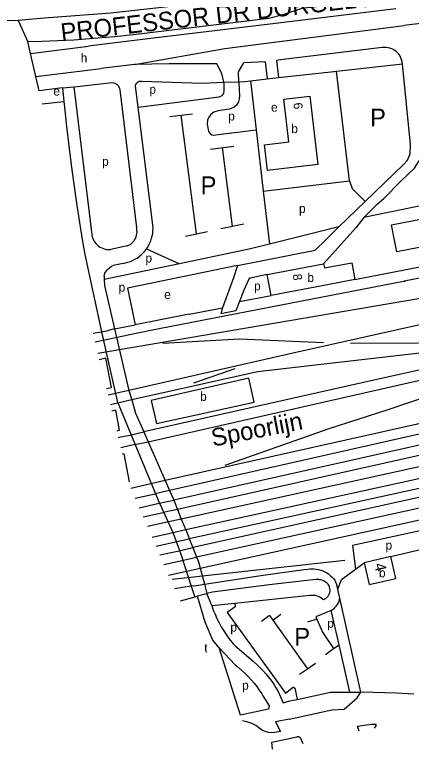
# Model space of a CAD drawing. Extents: x 161494 to 163033, y 383688 to 384862.
# Drawn here: x 161670.9 to 161849.3, y 383687.6 to 384018.2 of the extents above; entities that cross this region are included whole.
import ezdxf

# ---------------------------------------------------------------- set-up
doc = ezdxf.new("R2010")
doc.units = 0
for name, color, linetype in [('BLT_Basislijn', 7, 'Continuous'), ('BLT_Bebouwing', 7, 'Continuous'), ('BLT_Centroide', 7, 'Continuous'), ('BLT_Huisnummer', 7, 'Continuous'), ('BLT_Spoorlijn', 7, 'Continuous'), ('BLT_Straatnaam_hoofdweg', 7, 'Continuous'), ('BLT_Tekst_parkeren', 7, 'Continuous'), ('BLT_Vlakafsluiter', 7, 'Continuous'), ('BLT_Waternaam_spoorwegen', 7, 'Continuous')]:
    doc.layers.add(name, color=color, linetype=linetype)

msp = doc.modelspace()

# ---------------------------------------------------------------- linework, layer by layer
at = {"layer": 'BLT_Basislijn'}
for p, q in [((161765.4, 384002.94), (161846.02, 384013.32)), ((161677.97, 384000.74), (161704.06, 384004.05)), ((161836.15, 384003.38), (161790.39, 383997.8)), ((161783.48, 383996.91), (161773.88, 383996.43)), ((161783.48, 383996.91), (161784.41, 383989.24)), ((161680.37, 383990.38), (161709.82, 383994)), ((161724.78, 383995.79), (161709.82, 383994)), ((161815.65, 383992.77), (161845.3, 383996.01)), ((161784.41, 383989.24), (161789.51, 383989.82)), ((161789.51, 383989.82), (161814.36, 383992.62)), ((161814.36, 383992.62), (161815.65, 383992.77)), ((161697.71, 383985.74), (161714.8, 383987.57)), ((161774.42, 383988.12), (161776.92, 383988.4)), ((161776.92, 383988.4), (161784.41, 383989.24)), ((161692.4, 383985.17), (161681.87, 383983.86)), ((161692.4, 383985.17), (161697.71, 383985.74)), ((161692.4, 383985.17), (161693.01, 383979.05)), ((161705.81, 383917.86), (161697.71, 383985.74)), ((161726.41, 383976.48), (161725.22, 383985.97)), ((161683.23, 383977.98), (161693.01, 383979.05)), ((161733.03, 383923.45), (161726.41, 383976.48)), ((161740.72, 383972.29), (161750.81, 383973.53)), ((161752.62, 383919.49), (161745.77, 383972.91)), ((161758.96, 383957.71), (161769.41, 383959.02)), ((161764.19, 383958.36), (161768.74, 383922.99)), ((161782.69, 383938.81), (161785.47, 383914.89)), ((161885.02, 383938.77), (161827.95, 383926.88)), ((161763.6, 383921.88), (161773.88, 383924.1)), ((161827.95, 383926.88), (161824.29, 383922.18)), ((161747.64, 383918.45), (161757.6, 383920.53)), ((161824.29, 383922.18), (161809.85, 383905.98)), ((161721.43, 383914.07), (161714.06, 383912.5)), ((161730.16, 383912.76), (161744.95, 383906.09)), ((161719.64, 383906.25), (161715.18, 383905.36)), ((161711.14, 383900.44), (161711.12, 383899.03)), ((161772.01, 383889.06), (161786.28, 383891.79)), ((161772.01, 383889.06), (161770.41, 383884.87)), ((161749.36, 383883.42), (161764.42, 383886.22)), ((161764.42, 383886.22), (161763.53, 383883.59)), ((161770.41, 383884.87), (161763.53, 383883.59)), ((161749.36, 383883.42), (161725, 383878.57)), ((161715.71, 383876.72), (161725, 383878.57)), ((161706.18, 383874.78), (161709.88, 383875.43)), ((161709.88, 383875.43), (161712.87, 383876.09)), ((161715.71, 383876.72), (161712.87, 383876.09)), ((161715.71, 383876.72), (161722.27, 383849.1)), ((161824.12, 383768.62), (161828.04, 383771.52)), ((161751.61, 383761.13), (161756.21, 383761.84)), ((161756.21, 383761.84), (161757.29, 383757.74)), ((161807.74, 383763.94), (161806.33, 383763.91)), ((161814.83, 383763.63), (161815.99, 383760.97)), ((161750.28, 383760.93), (161742.81, 383759.77)), ((161751.61, 383761.13), (161750.28, 383760.93)), ((161750.28, 383760.93), (161751.84, 383756.07)), ((161816.29, 383759.59), (161815.99, 383760.97)), ((161817.18, 383755.63), (161816.29, 383759.59)), ((161751.84, 383756.07), (161745.25, 383754.16)), ((161753.15, 383756.45), (161751.84, 383756.07)), ((161753.12, 383756.56), (161757.29, 383757.74)), ((161753.15, 383756.45), (161753.12, 383756.56)), ((161759.49, 383752.21), (161757.29, 383757.74)), ((161769.84, 383753.32), (161803.68, 383756.95)), ((161826.62, 383713.33), (161817.18, 383755.63)), ((161759.49, 383752.21), (161769.84, 383753.32)), ((161786.97, 383745.72), (161790.65, 383748.43)), ((161814.84, 383742.96), (161813.21, 383750.07)), ((161785.52, 383747.76), (161781.9, 383745.1)), ((161785.52, 383747.76), (161786.97, 383745.72)), ((161786.97, 383745.72), (161802.57, 383723.78)), ((161806.73, 383746.14), (161802.54, 383744.71)), ((161816.75, 383734.59), (161814.84, 383742.96)), ((161762.87, 383733.18), (161770, 383725.61)), ((161772.4, 383702.86), (161762.87, 383733.18)), ((161770.81, 383733.46), (161778.34, 383727.09)), ((161810.62, 383730.25), (161814.34, 383732.89)), ((161814.34, 383732.89), (161816.75, 383734.59)), ((161821.62, 383713.28), (161816.75, 383734.59)), ((161802.57, 383723.78), (161806.25, 383726.35)), ((161799.02, 383721.31), (161802.57, 383723.78)), ((161821.62, 383713.28), (161826.62, 383713.33)), ((161794.69, 383709.36), (161797.89, 383710.05)), ((161785.06, 383705.7), (161772.4, 383702.86)), ((161799.31, 383692.83), (161800.51, 383690.22))]:
    msp.add_line(p, q, dxfattribs=at)
for points in [[(161959.65, 384027.27), (161916.99, 384022.03), (161846.02, 384013.32)], [(161835.45, 384025.19), (161800.1, 384020.96), (161791.09, 384018)], [(161739.79, 384021.71), (161714.13, 384018.78), (161684.15, 384016.64), (161672.41, 384015.53)], [(161842.35, 384020.82), (161788.17, 384014.19)], [(161791.09, 384018), (161785.18, 384016.45), (161725.46, 384009.27), (161715.75, 384008.14), (161704.48, 384007.29)], [(161538.09, 384009.41), (161555.72, 384011.42), (161572.01, 384013.43), (161594.77, 384014.55), (161646.33, 384015.67), (161672.41, 384015.53)], [(161788.17, 384014.19), (161729.55, 384007.15), (161704.06, 384004.05)], [(161704.48, 384007.29), (161697.55, 384006.73), (161683.11, 384006.03), (161676.77, 384005.94)], [(161845.3, 383996.01), (161845.2, 383996.81), (161845.03, 383997.59), (161844.77, 383998.35), (161844.45, 383999.08), (161844.05, 383999.78), (161843.59, 384000.43), (161843.06, 384001.03), (161842.48, 384001.58), (161841.84, 384002.06), (161841.16, 384002.48), (161840.44, 384002.83), (161839.68, 384003.11), (161838.91, 384003.3), (161838.12, 384003.43), (161837.32, 384003.47), (161836.52, 384003.43), (161836.15, 384003.38)], [(161771.76, 383988.01), (161771.62, 383992.51), (161773.88, 383996.43)], [(161790.39, 383997.8), (161788.61, 383997.58), (161789.51, 383989.82)], [(161761.84, 383996.07), (161759.15, 383996.01), (161740.4, 383996.01), (161724.78, 383995.79)], [(161765.01, 383987.72), (161764.11, 383991.69), (161761.84, 383996.07)], [(161828.5, 383934.11), (161845.73, 383950.79), (161847.49, 383952.7), (161848.71, 383955.6), (161848.84, 383959.68), (161845.3, 383996.01)], [(161821.42, 383943.33), (161815.65, 383992.77)], [(161714.8, 383987.57), (161715.37, 383987.54), (161715.95, 383987.35), (161716.58, 383987.09), (161717.02, 383986.75), (161717.43, 383986.31), (161717.75, 383985.73), (161718.06, 383985.01), (161718.19, 383984.4), (161725.67, 383922.33)], [(161725.22, 383985.97), (161725.27, 383986.4), (161725.4, 383986.81), (161725.61, 383987.2), (161725.88, 383987.54), (161726.2, 383987.82), (161726.58, 383988.04), (161726.99, 383988.19), (161727.41, 383988.26), (161727.85, 383988.25), (161728.12, 383988.2)], [(161726.41, 383976.48), (161762.92, 383981.14), (161764.25, 383981.79), (161764.96, 383982.73), (161765.17, 383984.02), (161765.17, 383986.98)], [(161728.12, 383988.2), (161755.13, 383987.31), (161765.01, 383987.72)], [(161771.76, 383988.01), (161771.98, 383981.27), (161771.59, 383978.98), (161770.62, 383977.47), (161769.46, 383976.46), (161767.4, 383975.71), (161762.43, 383974.92), (161760.45, 383974.32), (161759.07, 383973.31), (161758.14, 383972.07), (161757.57, 383970.66), (161757.46, 383968.89), (161757.83, 383966.47), (161758.06, 383965.57), (161758.81, 383964.62), (161759.59, 383964.14), (161760.41, 383963.97), (161761.31, 383964.05), (161779.48, 383966.37)], [(161765.01, 383987.72), (161771.76, 383988.01)], [(161765.17, 383986.98), (161765.01, 383987.72)], [(161771.76, 383988.01), (161774.42, 383988.12)], [(161776.92, 383988.4), (161779.48, 383966.37)], [(161693.01, 383979.05), (161693.26, 383976.51), (161694.18, 383967.85), (161695.19, 383959.19), (161696.28, 383950.55), (161697.45, 383941.92), (161698.7, 383933.3), (161700.02, 383924.69), (161701.43, 383916.1), (161702.44, 383910.17)], [(161779.48, 383966.37), (161782.69, 383938.81)], [(161827.95, 383926.88), (161834.08, 383932.99), (161836.84, 383935.47), (161844.57, 383943.19), (161850.77, 383949.03), (161853.48, 383953.65), (161854.18, 383957.29), (161854.11, 383960.54)], [(161782.69, 383938.81), (161821.42, 383943.33)], [(161821.42, 383943.33), (161822.72, 383939.9), (161828.5, 383934.11)], [(161816.71, 383922.7), (161828.5, 383934.11)], [(161721.43, 383914.07), (161722.11, 383914.37), (161722.75, 383914.74), (161723.36, 383915.17), (161723.91, 383915.67), (161724.4, 383916.23), (161724.83, 383916.83), (161725.2, 383917.48), (161725.49, 383918.16), (161725.7, 383918.87), (161725.84, 383919.6), (161725.9, 383920.35), (161725.88, 383921.09), (161725.79, 383921.83), (161725.67, 383922.33)], [(161730.16, 383912.76), (161730.63, 383913.44), (161731.2, 383914.41), (161731.7, 383915.42), (161732.12, 383916.46), (161732.48, 383917.54), (161732.75, 383918.63), (161732.95, 383919.74), (161733.07, 383920.86), (161733.1, 383921.99), (161733.06, 383923.11), (161733.03, 383923.45)], [(161771.14, 383905.24), (161805.99, 383912.22), (161810.62, 383916.75), (161816.71, 383922.7)], [(161816.71, 383922.7), (161785.47, 383914.89)], [(161705.81, 383917.86), (161706.11, 383917.12), (161706.49, 383916.41), (161706.94, 383915.74), (161707.45, 383915.12), (161708.02, 383914.55), (161708.64, 383914.05), (161709.31, 383913.6), (161710.02, 383913.23), (161710.77, 383912.93), (161711.54, 383912.7), (161712.33, 383912.55), (161713.13, 383912.48), (161713.94, 383912.49), (161714.06, 383912.5)], [(161785.47, 383914.89), (161776.93, 383912.75), (161744.95, 383906.09)], [(161823.92, 383898.93), (161900, 383913.85), (161900.32, 383913.91)], [(161719.64, 383906.25), (161720.75, 383906.46), (161721.84, 383906.75), (161722.91, 383907.12), (161723.94, 383907.56), (161724.95, 383908.07), (161725.91, 383908.66), (161726.83, 383909.31), (161727.71, 383910.02), (161728.52, 383910.8), (161729.29, 383911.63), (161729.99, 383912.51), (161730.16, 383912.76)], [(161702.44, 383910.17), (161709.88, 383875.43)], [(161744.95, 383906.09), (161711.12, 383899.03)], [(161711.14, 383900.44), (161711.47, 383901.84), (161712.12, 383902.86), (161712.7, 383903.51), (161713.47, 383904.27), (161714.37, 383904.93), (161715.18, 383905.36)], [(161771.14, 383905.24), (161721.66, 383895.11), (161725, 383878.57)], [(161771.14, 383905.24), (161769.36, 383899.7), (161764.42, 383886.22)], [(161784.5, 383901.17), (161776.8, 383899.56), (161776.18, 383899.17), (161773.98, 383894.25), (161772.01, 383889.06)], [(161711.12, 383899.03), (161711.3, 383896.22), (161715.71, 383876.72)], [(161709.88, 383875.43), (161716.94, 383844.28), (161735.43, 383799.67)], [(161712.24, 383849.9), (161714.42, 383850.38), (161711.92, 383863.63), (161708.89, 383862.9)], [(161722.27, 383849.1), (161723.5, 383844.79)], [(161723.5, 383844.79), (161725.19, 383838.83), (161728.91, 383830.42)], [(161716.82, 383830.88), (161718.06, 383831.16), (161716.36, 383840.13), (161714.58, 383839.73)], [(161728.91, 383830.42), (161730.85, 383826.01)], [(161730.85, 383826.01), (161738.59, 383808.47)], [(161722.45, 383807.93), (161720.07, 383820.53), (161719.26, 383820.35)], [(161738.59, 383808.47), (161740.55, 383804.02)], [(161740.55, 383804.02), (161742.16, 383800.39)], [(161735.43, 383799.67), (161742.16, 383784.86), (161745.64, 383775.39), (161750.28, 383760.93)], [(161742.16, 383800.39), (161742.42, 383799.74)], [(161742.42, 383799.74), (161744.09, 383795.55)], [(161744.09, 383795.55), (161745.83, 383791.21)], [(161884.2, 383794.32), (161863.54, 383790.11), (161858.12, 383786.9), (161822.86, 383779.21), (161824.12, 383768.62)], [(161840.05, 383774.26), (161854.57, 383777.72), (161858.96, 383784.17), (161863.29, 383787.44), (161870.76, 383790.62), (161884.2, 383794.32)], [(161745.83, 383791.21), (161747.79, 383786.3)], [(161747.79, 383786.3), (161748.99, 383783.33), (161749.42, 383782.25)], [(161749.42, 383782.25), (161751, 383778.31)], [(161751, 383778.31), (161752.71, 383774.04)], [(161752.71, 383774.04), (161753.58, 383771.89), (161754.32, 383769.07)], [(161754.32, 383769.07), (161756.21, 383761.84)], [(161756.21, 383761.84), (161782.59, 383765.89), (161800.98, 383768.52), (161802.67, 383768.63)], [(161802.67, 383768.63), (161803.65, 383768.76), (161804.64, 383768.82), (161805.63, 383768.79), (161806.61, 383768.69), (161807.58, 383768.51), (161808.54, 383768.24), (161809.47, 383767.91), (161810.37, 383767.49), (161811.23, 383767.01), (161812.05, 383766.46), (161812.83, 383765.85), (161813.55, 383765.17), (161814.21, 383764.44), (161814.83, 383763.63)], [(161816.29, 383759.59), (161817.93, 383764.04), (161824.12, 383768.62)], [(161806.33, 383763.91), (161785.37, 383761.6), (161759.88, 383758.27), (161757.29, 383757.74)], [(161807.74, 383763.94), (161808.36, 383763.91), (161808.97, 383763.79), (161809.56, 383763.6), (161810.12, 383763.33), (161810.64, 383763), (161811.11, 383762.6), (161811.52, 383762.14), (161811.88, 383761.63), (161812.17, 383761.08), (161812.38, 383760.5), (161812.51, 383759.9), (161812.57, 383759.28), (161812.55, 383758.66), (161812.45, 383758.05), (161812.27, 383757.46), (161812.01, 383756.89), (161811.68, 383756.37), (161811.3, 383755.89), (161810.85, 383755.46), (161810.35, 383755.1), (161809.85, 383754.82)], [(161762.87, 383733.18), (161760.01, 383736.61), (161756.58, 383744.81), (161753.15, 383756.45)], [(161803.68, 383756.95), (161804.45, 383757), (161805.21, 383756.98), (161805.97, 383756.88), (161806.72, 383756.7), (161807.44, 383756.44), (161808.13, 383756.11), (161808.79, 383755.71), (161809.39, 383755.24), (161809.85, 383754.82)], [(161813.21, 383750.07), (161813.88, 383750.48), (161814.51, 383750.96), (161815.09, 383751.5), (161815.61, 383752.1), (161816.07, 383752.74), (161816.46, 383753.43), (161816.78, 383754.16), (161817.02, 383754.91), (161817.18, 383755.63)], [(161759.49, 383752.21), (161760.21, 383750.24), (161761.01, 383748.31), (161761.87, 383746.41), (161762.81, 383744.54), (161763.82, 383742.71), (161764.9, 383740.92), (161766.05, 383739.17), (161767.26, 383737.46), (161768.54, 383735.81), (161769.21, 383734.98)], [(161769.84, 383753.32), (161770.02, 383751.66), (161766.5, 383749.09), (161792.65, 383712.84), (161796.26, 383715.7), (161796.55, 383715.12), (161796.84, 383715.22), (161797.89, 383710.05)], [(161813.21, 383750.07), (161806.35, 383747.19), (161806.73, 383746.14)], [(161806.73, 383746.14), (161809.29, 383740.24), (161814.34, 383732.89)], [(161769.21, 383734.98), (161770.24, 383733.97), (161770.81, 383733.46)], [(161770, 383725.61), (161771.56, 383724.38), (161773.06, 383723.1), (161774.52, 383721.75), (161775.91, 383720.35), (161777.25, 383718.89), (161778.53, 383717.37), (161779.74, 383715.81), (161780.9, 383714.2), (161781.98, 383712.54), (161782.51, 383711.68)], [(161778.34, 383727.09), (161779.8, 383725.79), (161781.21, 383724.44), (161782.56, 383723.03), (161783.86, 383721.57), (161785.09, 383720.05), (161786.26, 383718.49), (161787.37, 383716.88), (161788.4, 383715.23), (161789.37, 383713.53), (161790.04, 383712.26)], [(161790.04, 383712.26), (161791.66, 383708.55), (161794.69, 383709.36)], [(161794.26, 383701.14), (161813.54, 383705.31), (161819.06, 383705.61), (161824.86, 383710.76), (161826.62, 383713.33)], [(161797.89, 383710.05), (161812.91, 383713.27), (161821.62, 383713.28)], [(161850.45, 383712.34), (161842.81, 383712.87), (161826.62, 383713.33)], [(161782.51, 383711.68), (161785.41, 383707.16), (161785.06, 383705.7)], [(161794.26, 383701.14), (161788.24, 383699.98), (161790.37, 383695.59), (161787.87, 383695.2), (161786.44, 383695.04), (161785.01, 383695.14), (161783.52, 383695.53), (161782.32, 383696.1), (161781.22, 383696.84), (161779.29, 383698.21), (161777.49, 383699.13), (161775.36, 383699.89), (161773.28, 383700.32)], [(161829.1, 383698.53), (161831.39, 383698.85), (161833.24, 383698.85), (161833.3, 383698.15), (161832.5, 383697.13)], [(161825.82, 383695.69), (161825.61, 383696.14), (161825.13, 383697.98), (161829.1, 383698.53)], [(161786.91, 383687.57), (161786.57, 383690.72), (161797.85, 383693.22)], [(161797.85, 383693.22), (161798.15, 383693.31), (161798.47, 383693.31), (161798.77, 383693.24), (161799.05, 383693.09), (161799.31, 383692.83)]]:
    msp.add_lwpolyline(points, dxfattribs=at)
at = {"layer": 'BLT_Bebouwing'}
for p, q in [((161841.66, 383916.72), (161840.34, 383923.54)), ((161786.28, 383891.79), (161784.5, 383901.17)), ((161823.92, 383898.93), (161811.62, 383896.6)), ((161811.62, 383896.6), (161786.28, 383891.79)), ((161840.05, 383774.26), (161828.04, 383771.52)), ((161842.3, 383764.42), (161840.05, 383774.26))]:
    msp.add_line(p, q, dxfattribs=at)
for points in [[(161791.98, 383980.1), (161803.66, 383981.46), (161807.24, 383950.67), (161784.64, 383948.04), (161783.29, 383959.66), (161794.21, 383960.93), (161791.98, 383980.1)], [(161840.34, 383923.54), (161878.3, 383930.89), (161880.65, 383918.77), (161842.69, 383911.42), (161841.66, 383916.72)], [(161784.5, 383901.17), (161809.85, 383905.98)], [(161809.85, 383905.98), (161810.18, 383904.2)], [(161810.18, 383904.2), (161822.48, 383906.53), (161823.92, 383898.93)], [(161734.61, 383834.25), (161778.56, 383843.8), (161776.14, 383854.61), (161732.21, 383844.54), (161734.61, 383834.25)], [(161828.04, 383771.52), (161830.29, 383761.68)], [(161830.29, 383761.68), (161842.3, 383764.42)]]:
    msp.add_lwpolyline(points, dxfattribs=at)
at = {"layer": 'BLT_Spoorlijn'}
for p, q in [((161751.53, 383852.52), (161769.98, 383858.89)), ((161819.35, 383772.46), (161741.71, 383763.92))]:
    msp.add_line(p, q, dxfattribs=at)
for points in [[(162900.86, 384011.36), (162871.5, 384014.34), (162849.2, 384016.61), (162786.11, 384023.02), (162743.32, 384027.37), (162714.49, 384029.62), (162675.59, 384031.05), (162617.43, 384030.81), (162571.29, 384028.11), (162530.64, 384023.81), (162498.89, 384019.36), (162460.78, 384012.83), (162360.78, 383991.35), (162187.34, 383952.61), (162103.09, 383933.78), (162003.41, 383912.03), (161897.47, 383888.44), (161858.44, 383879.75), (161796.71, 383866.01)], [(162941.48, 383999.68), (162885.08, 384004.73), (162828.99, 384008.31), (162785.99, 384009.38), (162740.84, 384009.38), (162711.24, 384008.27), (162666.85, 384005.72), (162629.14, 384002.14), (162592.38, 383997.29), (162554.12, 383991.4), (162521.58, 383985.67), (162460.79, 383972.63), (162306.5, 383938.7), (162091.55, 383890.56), (161917.85, 383848.6), (161738.59, 383808.47)], [(162905.58, 383999.21), (162868.86, 384001.46), (162849.7, 384002.66), (162790.91, 384004.97), (162738.08, 384005.04), (162706.63, 384003.77), (162665.91, 384000.87), (162614.64, 383996.13), (162600, 383994.1), (162581.38, 383991.52), (162547.62, 383985.93), (162505.3, 383977.83), (162222.56, 383916.14), (162220.88, 383915.5), (162180.02, 383906.4), (162114.68, 383891.49), (162057.27, 383878.89), (162001, 383865.09), (161973.74, 383858.18), (161900, 383840.1), (161740.55, 383804.02)], [(161730.85, 383826.01), (161894.71, 383863.07), (161900, 383864.57), (161902.38, 383864.96), (161983.42, 383883.13), (162016.6, 383889.91), (162039.67, 383893.48), (162116.35, 383903.49), (162138.72, 383907.4), (162232.76, 383928.3), (162232.82, 383928.45), (162238.5, 383929.73), (162238.57, 383929.89), (162495.51, 383986.06), (162549.61, 383996.68)], [(162395.33, 383979.18), (162144.35, 383923.63), (161977.36, 383886.22), (161907.71, 383872.27), (161900, 383871.29), (161780.14, 383857.4), (161723.5, 383844.79)], [(161717.09, 383867.34), (161891.12, 383897), (161932.12, 383905.15), (161966.91, 383913.19), (162031.41, 383927.43), (162056.89, 383932.93), (162099.3, 383942.63)], [(161999.97, 383927.9), (161846.12, 383898.23), (161846.53, 383898.23)], [(162256.39, 383917.91), (162217.24, 383909.43), (162209.3, 383907.49), (162022.98, 383865.7), (161954.74, 383848.51), (161900, 383835.54), (161866.29, 383827.45), (161742.42, 383799.74)], [(161754.32, 383769.07), (161900, 383801.22), (162098.04, 383845.62), (162164.2, 383860.2), (162165.2, 383860.57), (162396.44, 383911.1), (162403.33, 383912.46)], [(161846.53, 383898.23), (161785.39, 383886.4), (161735.82, 383876.85), (161724, 383874.36)], [(162166.47, 383892.65), (162054.27, 383867.61), (161900, 383830.52), (161864.25, 383822.27), (161744.09, 383795.55)], [(161724, 383874.36), (161715.6, 383872.58)], [(161715.6, 383872.58), (161707.14, 383870.79)], [(161809.72, 383870.46), (161771.95, 383872.07), (161737.55, 383870.23)], [(161900, 383868.61), (161895.78, 383867.81), (161827.71, 383852.63), (161728.91, 383830.42)], [(161821.89, 383870.38), (161882.64, 383870.66)], [(161708.34, 383865.85), (161717.09, 383867.34)], [(161796.71, 383866.01), (161722.27, 383849.1)], [(162054.25, 383866.57), (162021.59, 383855.48), (161912.53, 383828.39), (161900, 383825.65), (161877.44, 383820.08), (161745.83, 383791.21)], [(162130.47, 383867.03), (161900, 383815.76), (161885.6, 383812.15), (161749.42, 383782.25)], [(161912.76, 383865.42), (161838.19, 383840.24), (161812.17, 383831.86), (161765.38, 383815.26)], [(162061.12, 383856.79), (161900, 383820.16), (161877.93, 383814.9), (161747.79, 383786.3)], [(162091.56, 383853.64), (161899.96, 383811.43), (161751, 383778.31)], [(161722.27, 383849.1), (161712.89, 383846.97)], [(161723.5, 383844.79), (161713.93, 383842.66)], [(162050.18, 383839.64), (161899.96, 383806.47), (161752.71, 383774.04)], [(161717.48, 383827.96), (161718.64, 383828.22), (161722.7, 383828.98)], [(161722.7, 383828.98), (161728.91, 383830.42)], [(161724.93, 383824.67), (161718.61, 383823.28)], [(161724.93, 383824.67), (161730.85, 383826.01)], [(161738.59, 383808.47), (161723.1, 383805.01)], [(161725.02, 383800.59), (161734.07, 383802.61)], [(161740.55, 383804.02), (161734.07, 383802.61)], [(161726.9, 383796.27), (161735.88, 383798.27)], [(161735.88, 383798.27), (161742.42, 383799.74)], [(161744.09, 383795.55), (161737.67, 383794.13)], [(161728.71, 383792.12), (161737.67, 383794.13)], [(161739.43, 383789.81), (161730.58, 383787.84)], [(161745.83, 383791.21), (161739.43, 383789.81)], [(161741.47, 383784.88), (161732.71, 383782.94)], [(161747.79, 383786.3), (161741.47, 383784.88)], [(161743.21, 383780.87), (161749.42, 383782.25)], [(161734.46, 383778.93), (161743.21, 383780.87)], [(161744.83, 383776.95), (161751, 383778.31)], [(161736.16, 383775.02), (161744.83, 383776.95)], [(161738.01, 383770.78), (161746.82, 383772.73)], [(161746.82, 383772.73), (161752.71, 383774.04)], [(161748.88, 383767.87), (161754.32, 383769.07)], [(161740.12, 383765.93), (161748.88, 383767.87)]]:
    msp.add_lwpolyline(points, dxfattribs=at)
at = {"layer": 'BLT_Vlakafsluiter'}
for p, q in [((161672.41, 384015.53), (161676.77, 384005.94)), ((161677.97, 384000.74), (161676.77, 384005.94)), ((161680.37, 383990.38), (161677.97, 384000.74)), ((161724.78, 383995.79), (161765.4, 384002.94)), ((161681.87, 383983.86), (161680.37, 383990.38))]:
    msp.add_line(p, q, dxfattribs=at)

# ---------------------------------------------------------------- texts
at = {"layer": 'BLT_Centroide'}
for s, p in [('h', (161700.58, 383996.74)), ('e', (161688.27, 383981.76)), ('p', (161731.47, 383982.61)), ('e', (161786.16, 383974.53)), ('p', (161766.91, 383970.55)), ('b', (161795.27, 383964.88)), ('p', (161710.2, 383950.15)), ('p', (161798.77, 383928.94)), ('p', (161729.71, 383906.63)), ('b', (161802.52, 383897.89)), ('p', (161778.55, 383894.1)), ('p', (161717.63, 383893.56)), ('e', (161738.13, 383890.26)), ('b', (161754.28, 383844.38)), ('p', (161837.68, 383777.46)), ('b', (161834.71, 383765)), ('p', (161811.45, 383742.26)), ('p', (161767.88, 383740.55)), ('t', (161756.14, 383731.17)), ('p', (161773.18, 383714.41))]:
    msp.add_text(s, height=4, dxfattribs=at).set_placement(p)
at = {"layer": 'BLT_Huisnummer'}
for s, height, rotation, p in [('6', 4, 276.632, (161796.2, 383978.38)), ('8', 4, 276.6323, (161795.92, 383901.3)), ('4', 5, 282.5724, (161832.55, 383770.85))]:
    msp.add_text(s, height=height, rotation=rotation, dxfattribs=at).set_placement(p)
at = {"layer": 'BLT_Straatnaam_hoofdweg'}
msp.add_text('PROFESSOR DR DORGELOLAAN', height=8, rotation=6.4466, dxfattribs=at).set_placement((161692.04, 384006.18))
at = {"layer": 'BLT_Tekst_parkeren'}
for p in [(161830.69, 383967.91), (161754.49, 383937.38), (161796.63, 383734.23)]:
    msp.add_text('P', height=8, dxfattribs=at).set_placement(p)
at = {"layer": 'BLT_Waternaam_spoorwegen'}
msp.add_text('Spoorlijn', height=8, rotation=11, dxfattribs=at).set_placement((161760.09, 383823.73))

doc.saveas('drawing.dxf')
